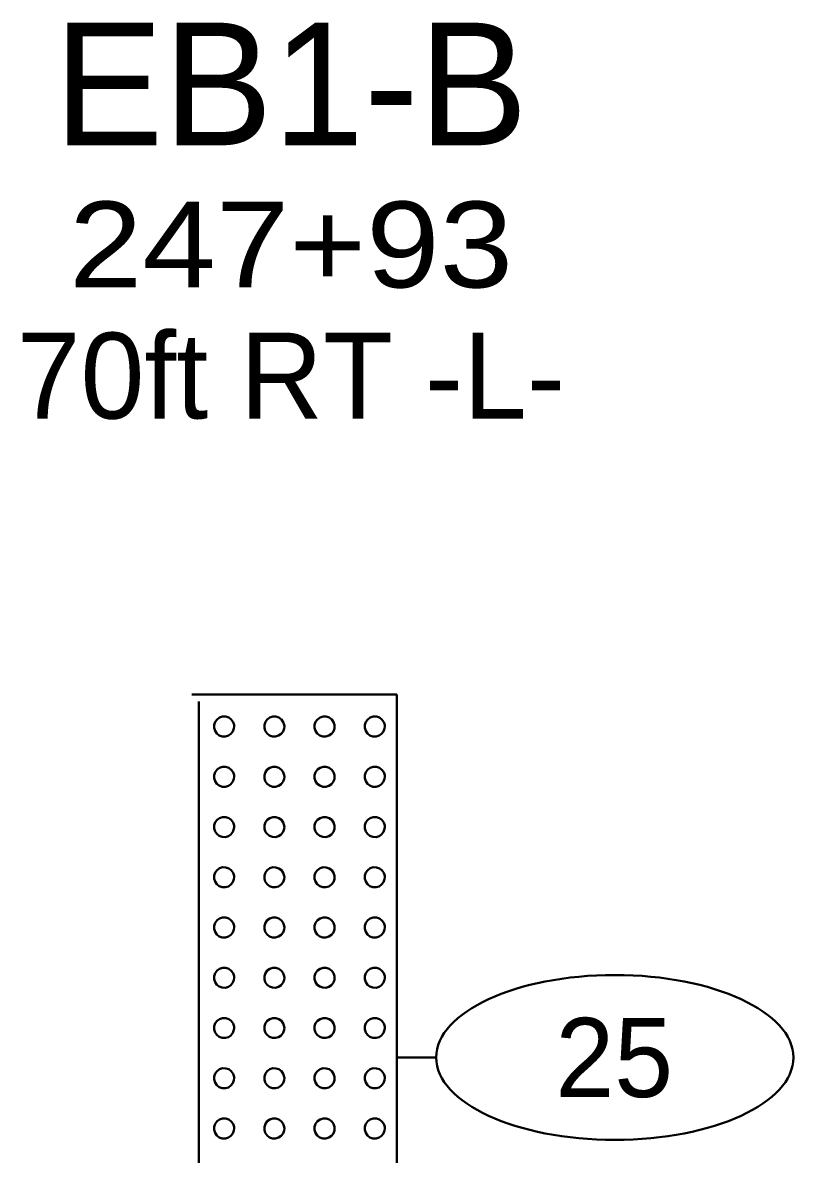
# Model space of a CAD drawing. Extents: x -76 to 974, y -1080 to -735.
# Drawn here: x -41.9 to -32.15, y -771.53 to -757.23 of the extents above; entities that cross this region are included whole.
import ezdxf
from ezdxf.enums import TextEntityAlignment as Align

# ---------------------------------------------------------------- set-up
doc = ezdxf.new("R2010")
doc.units = 0
doc.header["$LTSCALE"] = 0.36
doc.layers.add('27', color=7, linetype='Continuous', lineweight=40)

msp = doc.modelspace()

# ---------------------------------------------------------------- linework, layer by layer
at = {"layer": '27'}
for p, q in [((-39.7556, -765.7164), (-37.1667, -765.7164)), ((-37.1667, -777.8053), (-37.1667, -765.7164)), ((-39.6667, -765.8053), (-39.6667, -777.8053)), ((-36.6667, -770.3053), (-37.1667, -770.3053))]:
    msp.add_line(p, q, dxfattribs=at)
for points in [[(-39.2221, -766.1228), (-39.2237, -766.103), (-39.2358, -766.0654), (-39.2589, -766.0333), (-39.2908, -766.0099), (-39.3284, -765.9974), (-39.3679, -765.9971), (-39.4057, -766.0089), (-39.4379, -766.0317), (-39.4616, -766.0634), (-39.4744, -766.1008), (-39.4751, -766.1404), (-39.4636, -766.1782), (-39.4411, -766.2107), (-39.4096, -766.2347), (-39.3723, -766.2478), (-39.3327, -766.2489), (-39.2948, -766.2377), (-39.2621, -766.2154), (-39.2379, -766.1841), (-39.2244, -766.1469)], [(-38.5871, -766.1228), (-38.5887, -766.103), (-38.6008, -766.0654), (-38.6239, -766.0333), (-38.6558, -766.0099), (-38.6934, -765.9974), (-38.7329, -765.9971), (-38.7707, -766.0089), (-38.8029, -766.0317), (-38.8266, -766.0634), (-38.8394, -766.1008), (-38.8401, -766.1404), (-38.8286, -766.1782), (-38.8061, -766.2107), (-38.7746, -766.2347), (-38.7373, -766.2478), (-38.6977, -766.2489), (-38.6598, -766.2377), (-38.6271, -766.2154), (-38.6029, -766.1841), (-38.5894, -766.1469)], [(-37.9521, -766.1228), (-37.9537, -766.103), (-37.9658, -766.0654), (-37.9889, -766.0333), (-38.0208, -766.0099), (-38.0584, -765.9974), (-38.0979, -765.9971), (-38.1357, -766.0089), (-38.1679, -766.0317), (-38.1916, -766.0634), (-38.2044, -766.1008), (-38.2051, -766.1404), (-38.1936, -766.1782), (-38.1711, -766.2107), (-38.1396, -766.2347), (-38.1023, -766.2478), (-38.0627, -766.2489), (-38.0248, -766.2377), (-37.9921, -766.2154), (-37.9679, -766.1841), (-37.9544, -766.1469)], [(-37.3171, -766.1228), (-37.3187, -766.103), (-37.3308, -766.0654), (-37.3539, -766.0333), (-37.3858, -766.0099), (-37.4234, -765.9974), (-37.4629, -765.9971), (-37.5007, -766.0089), (-37.5329, -766.0317), (-37.5566, -766.0634), (-37.5694, -766.1008), (-37.5701, -766.1404), (-37.5586, -766.1782), (-37.5361, -766.2107), (-37.5046, -766.2347), (-37.4673, -766.2478), (-37.4277, -766.2489), (-37.3898, -766.2377), (-37.3571, -766.2154), (-37.3329, -766.1841), (-37.3194, -766.1469)], [(-39.2221, -766.7578), (-39.2237, -766.738), (-39.2358, -766.7004), (-39.2589, -766.6683), (-39.2908, -766.6449), (-39.3284, -766.6324), (-39.3679, -766.6321), (-39.4057, -766.6439), (-39.4379, -766.6667), (-39.4616, -766.6984), (-39.4744, -766.7358), (-39.4751, -766.7754), (-39.4636, -766.8132), (-39.4411, -766.8457), (-39.4096, -766.8697), (-39.3723, -766.8828), (-39.3327, -766.8839), (-39.2948, -766.8727), (-39.2621, -766.8504), (-39.2379, -766.8191), (-39.2244, -766.7819)], [(-38.5871, -766.7578), (-38.5887, -766.738), (-38.6008, -766.7004), (-38.6239, -766.6683), (-38.6558, -766.6449), (-38.6934, -766.6324), (-38.7329, -766.6321), (-38.7707, -766.6439), (-38.8029, -766.6667), (-38.8266, -766.6984), (-38.8394, -766.7358), (-38.8401, -766.7754), (-38.8286, -766.8132), (-38.8061, -766.8457), (-38.7746, -766.8697), (-38.7373, -766.8828), (-38.6977, -766.8839), (-38.6598, -766.8727), (-38.6271, -766.8504), (-38.6029, -766.8191), (-38.5894, -766.7819)], [(-37.9521, -766.7578), (-37.9537, -766.738), (-37.9658, -766.7004), (-37.9889, -766.6683), (-38.0208, -766.6449), (-38.0584, -766.6324), (-38.0979, -766.6321), (-38.1357, -766.6439), (-38.1679, -766.6667), (-38.1916, -766.6984), (-38.2044, -766.7358), (-38.2051, -766.7754), (-38.1936, -766.8132), (-38.1711, -766.8457), (-38.1396, -766.8697), (-38.1023, -766.8828), (-38.0627, -766.8839), (-38.0248, -766.8727), (-37.9921, -766.8504), (-37.9679, -766.8191), (-37.9544, -766.7819)], [(-37.3171, -766.7578), (-37.3187, -766.738), (-37.3308, -766.7004), (-37.3539, -766.6683), (-37.3858, -766.6449), (-37.4234, -766.6324), (-37.4629, -766.6321), (-37.5007, -766.6439), (-37.5329, -766.6667), (-37.5566, -766.6984), (-37.5694, -766.7358), (-37.5701, -766.7754), (-37.5586, -766.8132), (-37.5361, -766.8457), (-37.5046, -766.8697), (-37.4673, -766.8828), (-37.4277, -766.8839), (-37.3898, -766.8727), (-37.3571, -766.8504), (-37.3329, -766.8191), (-37.3194, -766.7819)], [(-39.2221, -767.3928), (-39.2237, -767.373), (-39.2358, -767.3354), (-39.2589, -767.3033), (-39.2908, -767.2799), (-39.3284, -767.2674), (-39.3679, -767.2671), (-39.4057, -767.2789), (-39.4379, -767.3017), (-39.4616, -767.3334), (-39.4744, -767.3708), (-39.4751, -767.4104), (-39.4636, -767.4482), (-39.4411, -767.4807), (-39.4096, -767.5047), (-39.3723, -767.5178), (-39.3327, -767.5189), (-39.2948, -767.5077), (-39.2621, -767.4854), (-39.2379, -767.4541), (-39.2244, -767.4169)], [(-38.5871, -767.3928), (-38.5887, -767.373), (-38.6008, -767.3354), (-38.6239, -767.3033), (-38.6558, -767.2799), (-38.6934, -767.2674), (-38.7329, -767.2671), (-38.7707, -767.2789), (-38.8029, -767.3017), (-38.8266, -767.3334), (-38.8394, -767.3708), (-38.8401, -767.4104), (-38.8286, -767.4482), (-38.8061, -767.4807), (-38.7746, -767.5047), (-38.7373, -767.5178), (-38.6977, -767.5189), (-38.6598, -767.5077), (-38.6271, -767.4854), (-38.6029, -767.4541), (-38.5894, -767.4169)], [(-37.9521, -767.3928), (-37.9537, -767.373), (-37.9658, -767.3354), (-37.9889, -767.3033), (-38.0208, -767.2799), (-38.0584, -767.2674), (-38.0979, -767.2671), (-38.1357, -767.2789), (-38.1679, -767.3017), (-38.1916, -767.3334), (-38.2044, -767.3708), (-38.2051, -767.4104), (-38.1936, -767.4482), (-38.1711, -767.4807), (-38.1396, -767.5047), (-38.1023, -767.5178), (-38.0627, -767.5189), (-38.0248, -767.5077), (-37.9921, -767.4854), (-37.9679, -767.4541), (-37.9544, -767.4169)], [(-37.3171, -767.3928), (-37.3187, -767.373), (-37.3308, -767.3354), (-37.3539, -767.3033), (-37.3858, -767.2799), (-37.4234, -767.2674), (-37.4629, -767.2671), (-37.5007, -767.2789), (-37.5329, -767.3017), (-37.5566, -767.3334), (-37.5694, -767.3708), (-37.5701, -767.4104), (-37.5586, -767.4482), (-37.5361, -767.4807), (-37.5046, -767.5047), (-37.4673, -767.5178), (-37.4277, -767.5189), (-37.3898, -767.5077), (-37.3571, -767.4854), (-37.3329, -767.4541), (-37.3194, -767.4169)], [(-39.2221, -768.0278), (-39.2237, -768.008), (-39.2358, -767.9704), (-39.2589, -767.9383), (-39.2908, -767.9149), (-39.3284, -767.9024), (-39.3679, -767.9021), (-39.4057, -767.9139), (-39.4379, -767.9367), (-39.4616, -767.9684), (-39.4744, -768.0058), (-39.4751, -768.0454), (-39.4636, -768.0832), (-39.4411, -768.1157), (-39.4096, -768.1397), (-39.3723, -768.1528), (-39.3327, -768.1539), (-39.2948, -768.1427), (-39.2621, -768.1204), (-39.2379, -768.0891), (-39.2244, -768.0519)], [(-38.5871, -768.0278), (-38.5887, -768.008), (-38.6008, -767.9704), (-38.6239, -767.9383), (-38.6558, -767.9149), (-38.6934, -767.9024), (-38.7329, -767.9021), (-38.7707, -767.9139), (-38.8029, -767.9367), (-38.8266, -767.9684), (-38.8394, -768.0058), (-38.8401, -768.0454), (-38.8286, -768.0832), (-38.8061, -768.1157), (-38.7746, -768.1397), (-38.7373, -768.1528), (-38.6977, -768.1539), (-38.6598, -768.1427), (-38.6271, -768.1204), (-38.6029, -768.0891), (-38.5894, -768.0519)], [(-37.9521, -768.0278), (-37.9537, -768.008), (-37.9658, -767.9704), (-37.9889, -767.9383), (-38.0208, -767.9149), (-38.0584, -767.9024), (-38.0979, -767.9021), (-38.1357, -767.9139), (-38.1679, -767.9367), (-38.1916, -767.9684), (-38.2044, -768.0058), (-38.2051, -768.0454), (-38.1936, -768.0832), (-38.1711, -768.1157), (-38.1396, -768.1397), (-38.1023, -768.1528), (-38.0627, -768.1539), (-38.0248, -768.1427), (-37.9921, -768.1204), (-37.9679, -768.0891), (-37.9544, -768.0519)], [(-37.3171, -768.0278), (-37.3187, -768.008), (-37.3308, -767.9704), (-37.3539, -767.9383), (-37.3858, -767.9149), (-37.4234, -767.9024), (-37.4629, -767.9021), (-37.5007, -767.9139), (-37.5329, -767.9367), (-37.5566, -767.9684), (-37.5694, -768.0058), (-37.5701, -768.0454), (-37.5586, -768.0832), (-37.5361, -768.1157), (-37.5046, -768.1397), (-37.4673, -768.1528), (-37.4277, -768.1539), (-37.3898, -768.1427), (-37.3571, -768.1204), (-37.3329, -768.0891), (-37.3194, -768.0519)], [(-39.2221, -768.6628), (-39.2237, -768.643), (-39.2358, -768.6054), (-39.2589, -768.5733), (-39.2908, -768.5499), (-39.3284, -768.5374), (-39.3679, -768.5371), (-39.4057, -768.5489), (-39.4379, -768.5717), (-39.4616, -768.6034), (-39.4744, -768.6408), (-39.4751, -768.6804), (-39.4636, -768.7182), (-39.4411, -768.7507), (-39.4096, -768.7747), (-39.3723, -768.7878), (-39.3327, -768.7889), (-39.2948, -768.7777), (-39.2621, -768.7554), (-39.2379, -768.7241), (-39.2244, -768.6869)], [(-38.5871, -768.6628), (-38.5887, -768.643), (-38.6008, -768.6054), (-38.6239, -768.5733), (-38.6558, -768.5499), (-38.6934, -768.5374), (-38.7329, -768.5371), (-38.7707, -768.5489), (-38.8029, -768.5717), (-38.8266, -768.6034), (-38.8394, -768.6408), (-38.8401, -768.6804), (-38.8286, -768.7182), (-38.8061, -768.7507), (-38.7746, -768.7747), (-38.7373, -768.7878), (-38.6977, -768.7889), (-38.6598, -768.7777), (-38.6271, -768.7554), (-38.6029, -768.7241), (-38.5894, -768.6869)], [(-37.9521, -768.6628), (-37.9537, -768.643), (-37.9658, -768.6054), (-37.9889, -768.5733), (-38.0208, -768.5499), (-38.0584, -768.5374), (-38.0979, -768.5371), (-38.1357, -768.5489), (-38.1679, -768.5717), (-38.1916, -768.6034), (-38.2044, -768.6408), (-38.2051, -768.6804), (-38.1936, -768.7182), (-38.1711, -768.7507), (-38.1396, -768.7747), (-38.1023, -768.7878), (-38.0627, -768.7889), (-38.0248, -768.7777), (-37.9921, -768.7554), (-37.9679, -768.7241), (-37.9544, -768.6869)], [(-37.3171, -768.6628), (-37.3187, -768.643), (-37.3308, -768.6054), (-37.3539, -768.5733), (-37.3858, -768.5499), (-37.4234, -768.5374), (-37.4629, -768.5371), (-37.5007, -768.5489), (-37.5329, -768.5717), (-37.5566, -768.6034), (-37.5694, -768.6408), (-37.5701, -768.6804), (-37.5586, -768.7182), (-37.5361, -768.7507), (-37.5046, -768.7747), (-37.4673, -768.7878), (-37.4277, -768.7889), (-37.3898, -768.7777), (-37.3571, -768.7554), (-37.3329, -768.7241), (-37.3194, -768.6869)], [(-39.2221, -769.2978), (-39.2237, -769.278), (-39.2358, -769.2404), (-39.2589, -769.2083), (-39.2908, -769.1849), (-39.3284, -769.1724), (-39.3679, -769.1721), (-39.4057, -769.1839), (-39.4379, -769.2067), (-39.4616, -769.2384), (-39.4744, -769.2758), (-39.4751, -769.3154), (-39.4636, -769.3532), (-39.4411, -769.3857), (-39.4096, -769.4097), (-39.3723, -769.4228), (-39.3327, -769.4239), (-39.2948, -769.4127), (-39.2621, -769.3904), (-39.2379, -769.3591), (-39.2244, -769.3219)], [(-38.5871, -769.2978), (-38.5887, -769.278), (-38.6008, -769.2404), (-38.6239, -769.2083), (-38.6558, -769.1849), (-38.6934, -769.1724), (-38.7329, -769.1721), (-38.7707, -769.1839), (-38.8029, -769.2067), (-38.8266, -769.2384), (-38.8394, -769.2758), (-38.8401, -769.3154), (-38.8286, -769.3532), (-38.8061, -769.3857), (-38.7746, -769.4097), (-38.7373, -769.4228), (-38.6977, -769.4239), (-38.6598, -769.4127), (-38.6271, -769.3904), (-38.6029, -769.3591), (-38.5894, -769.3219)], [(-37.9521, -769.2978), (-37.9537, -769.278), (-37.9658, -769.2404), (-37.9889, -769.2083), (-38.0208, -769.1849), (-38.0584, -769.1724), (-38.0979, -769.1721), (-38.1357, -769.1839), (-38.1679, -769.2067), (-38.1916, -769.2384), (-38.2044, -769.2758), (-38.2051, -769.3154), (-38.1936, -769.3532), (-38.1711, -769.3857), (-38.1396, -769.4097), (-38.1023, -769.4228), (-38.0627, -769.4239), (-38.0248, -769.4127), (-37.9921, -769.3904), (-37.9679, -769.3591), (-37.9544, -769.3219)], [(-37.3171, -769.2978), (-37.3187, -769.278), (-37.3308, -769.2404), (-37.3539, -769.2083), (-37.3858, -769.1849), (-37.4234, -769.1724), (-37.4629, -769.1721), (-37.5007, -769.1839), (-37.5329, -769.2067), (-37.5566, -769.2384), (-37.5694, -769.2758), (-37.5701, -769.3154), (-37.5586, -769.3532), (-37.5361, -769.3857), (-37.5046, -769.4097), (-37.4673, -769.4228), (-37.4277, -769.4239), (-37.3898, -769.4127), (-37.3571, -769.3904), (-37.3329, -769.3591), (-37.3194, -769.3219)], [(-39.2221, -769.9328), (-39.2237, -769.913), (-39.2358, -769.8754), (-39.2589, -769.8433), (-39.2908, -769.8199), (-39.3284, -769.8074), (-39.3679, -769.8071), (-39.4057, -769.8189), (-39.4379, -769.8417), (-39.4616, -769.8734), (-39.4744, -769.9108), (-39.4751, -769.9504), (-39.4636, -769.9882), (-39.4411, -770.0207), (-39.4096, -770.0447), (-39.3723, -770.0578), (-39.3327, -770.0589), (-39.2948, -770.0477), (-39.2621, -770.0254), (-39.2379, -769.9941), (-39.2244, -769.9569)], [(-38.5871, -769.9328), (-38.5887, -769.913), (-38.6008, -769.8754), (-38.6239, -769.8433), (-38.6558, -769.8199), (-38.6934, -769.8074), (-38.7329, -769.8071), (-38.7707, -769.8189), (-38.8029, -769.8417), (-38.8266, -769.8734), (-38.8394, -769.9108), (-38.8401, -769.9504), (-38.8286, -769.9882), (-38.8061, -770.0207), (-38.7746, -770.0447), (-38.7373, -770.0578), (-38.6977, -770.0589), (-38.6598, -770.0477), (-38.6271, -770.0254), (-38.6029, -769.9941), (-38.5894, -769.9569)], [(-37.9521, -769.9328), (-37.9537, -769.913), (-37.9658, -769.8754), (-37.9889, -769.8433), (-38.0208, -769.8199), (-38.0584, -769.8074), (-38.0979, -769.8071), (-38.1357, -769.8189), (-38.1679, -769.8417), (-38.1916, -769.8734), (-38.2044, -769.9108), (-38.2051, -769.9504), (-38.1936, -769.9882), (-38.1711, -770.0207), (-38.1396, -770.0447), (-38.1023, -770.0578), (-38.0627, -770.0589), (-38.0248, -770.0477), (-37.9921, -770.0254), (-37.9679, -769.9941), (-37.9544, -769.9569)], [(-37.3171, -769.9328), (-37.3187, -769.913), (-37.3308, -769.8754), (-37.3539, -769.8433), (-37.3858, -769.8199), (-37.4234, -769.8074), (-37.4629, -769.8071), (-37.5007, -769.8189), (-37.5329, -769.8417), (-37.5566, -769.8734), (-37.5694, -769.9108), (-37.5701, -769.9504), (-37.5586, -769.9882), (-37.5361, -770.0207), (-37.5046, -770.0447), (-37.4673, -770.0578), (-37.4277, -770.0589), (-37.3898, -770.0477), (-37.3571, -770.0254), (-37.3329, -769.9941), (-37.3194, -769.9569)], [(-39.2221, -770.5678), (-39.2237, -770.548), (-39.2358, -770.5104), (-39.2589, -770.4783), (-39.2908, -770.4549), (-39.3284, -770.4424), (-39.3679, -770.4421), (-39.4057, -770.4539), (-39.4379, -770.4767), (-39.4616, -770.5084), (-39.4744, -770.5458), (-39.4751, -770.5854), (-39.4636, -770.6232), (-39.4411, -770.6557), (-39.4096, -770.6797), (-39.3723, -770.6928), (-39.3327, -770.6939), (-39.2948, -770.6827), (-39.2621, -770.6604), (-39.2379, -770.6291), (-39.2244, -770.5919)], [(-38.5871, -770.5678), (-38.5887, -770.548), (-38.6008, -770.5104), (-38.6239, -770.4783), (-38.6558, -770.4549), (-38.6934, -770.4424), (-38.7329, -770.4421), (-38.7707, -770.4539), (-38.8029, -770.4767), (-38.8266, -770.5084), (-38.8394, -770.5458), (-38.8401, -770.5854), (-38.8286, -770.6232), (-38.8061, -770.6557), (-38.7746, -770.6797), (-38.7373, -770.6928), (-38.6977, -770.6939), (-38.6598, -770.6827), (-38.6271, -770.6604), (-38.6029, -770.6291), (-38.5894, -770.5919)], [(-37.9521, -770.5678), (-37.9537, -770.548), (-37.9658, -770.5104), (-37.9889, -770.4783), (-38.0208, -770.4549), (-38.0584, -770.4424), (-38.0979, -770.4421), (-38.1357, -770.4539), (-38.1679, -770.4767), (-38.1916, -770.5084), (-38.2044, -770.5458), (-38.2051, -770.5854), (-38.1936, -770.6232), (-38.1711, -770.6557), (-38.1396, -770.6797), (-38.1023, -770.6928), (-38.0627, -770.6939), (-38.0248, -770.6827), (-37.9921, -770.6604), (-37.9679, -770.6291), (-37.9544, -770.5919)], [(-37.3171, -770.5678), (-37.3187, -770.548), (-37.3308, -770.5104), (-37.3539, -770.4783), (-37.3858, -770.4549), (-37.4234, -770.4424), (-37.4629, -770.4421), (-37.5007, -770.4539), (-37.5329, -770.4767), (-37.5566, -770.5084), (-37.5694, -770.5458), (-37.5701, -770.5854), (-37.5586, -770.6232), (-37.5361, -770.6557), (-37.5046, -770.6797), (-37.4673, -770.6928), (-37.4277, -770.6939), (-37.3898, -770.6827), (-37.3571, -770.6604), (-37.3329, -770.6291), (-37.3194, -770.5919)], [(-39.2221, -771.2028), (-39.2237, -771.183), (-39.2358, -771.1454), (-39.2589, -771.1133), (-39.2908, -771.0899), (-39.3284, -771.0774), (-39.3679, -771.0771), (-39.4057, -771.0889), (-39.4379, -771.1117), (-39.4616, -771.1434), (-39.4744, -771.1808), (-39.4751, -771.2204), (-39.4636, -771.2582), (-39.4411, -771.2907), (-39.4096, -771.3147), (-39.3723, -771.3278), (-39.3327, -771.3289), (-39.2948, -771.3177), (-39.2621, -771.2954), (-39.2379, -771.2641), (-39.2244, -771.2269)], [(-38.5871, -771.2028), (-38.5887, -771.183), (-38.6008, -771.1454), (-38.6239, -771.1133), (-38.6558, -771.0899), (-38.6934, -771.0774), (-38.7329, -771.0771), (-38.7707, -771.0889), (-38.8029, -771.1117), (-38.8266, -771.1434), (-38.8394, -771.1808), (-38.8401, -771.2204), (-38.8286, -771.2582), (-38.8061, -771.2907), (-38.7746, -771.3147), (-38.7373, -771.3278), (-38.6977, -771.3289), (-38.6598, -771.3177), (-38.6271, -771.2954), (-38.6029, -771.2641), (-38.5894, -771.2269)], [(-37.9521, -771.2028), (-37.9537, -771.183), (-37.9658, -771.1454), (-37.9889, -771.1133), (-38.0208, -771.0899), (-38.0584, -771.0774), (-38.0979, -771.0771), (-38.1357, -771.0889), (-38.1679, -771.1117), (-38.1916, -771.1434), (-38.2044, -771.1808), (-38.2051, -771.2204), (-38.1936, -771.2582), (-38.1711, -771.2907), (-38.1396, -771.3147), (-38.1023, -771.3278), (-38.0627, -771.3289), (-38.0248, -771.3177), (-37.9921, -771.2954), (-37.9679, -771.2641), (-37.9544, -771.2269)], [(-37.3171, -771.2028), (-37.3187, -771.183), (-37.3308, -771.1454), (-37.3539, -771.1133), (-37.3858, -771.0899), (-37.4234, -771.0774), (-37.4629, -771.0771), (-37.5007, -771.0889), (-37.5329, -771.1117), (-37.5566, -771.1434), (-37.5694, -771.1808), (-37.5701, -771.2204), (-37.5586, -771.2582), (-37.5361, -771.2907), (-37.5046, -771.3147), (-37.4673, -771.3278), (-37.4277, -771.3289), (-37.3898, -771.3177), (-37.3571, -771.2954), (-37.3329, -771.2641), (-37.3194, -771.2269)]]:
    msp.add_lwpolyline(points, close=True, dxfattribs=at)
msp.add_ellipse((-34.4093, -770.3053), major_axis=(2.2574, 0), ratio=0.461538, dxfattribs=at)

# ---------------------------------------------------------------- texts
for s, height, p in [('EB1-B', 1.55, (-38.504, -758.7768)), ('70ft RT -L-', 1.085, (-38.5037, -762.2304)), ('25', 1, (-34.4168, -770.8053))]:
    msp.add_text(s, height=height, dxfattribs=at).set_placement(p, align=Align.CENTER)
at = {"layer": '27', "width": 1.15}
msp.add_text('247+93', height=1.085, dxfattribs=at).set_placement((-38.5031, -760.5734), align=Align.CENTER)

doc.saveas('drawing.dxf')
